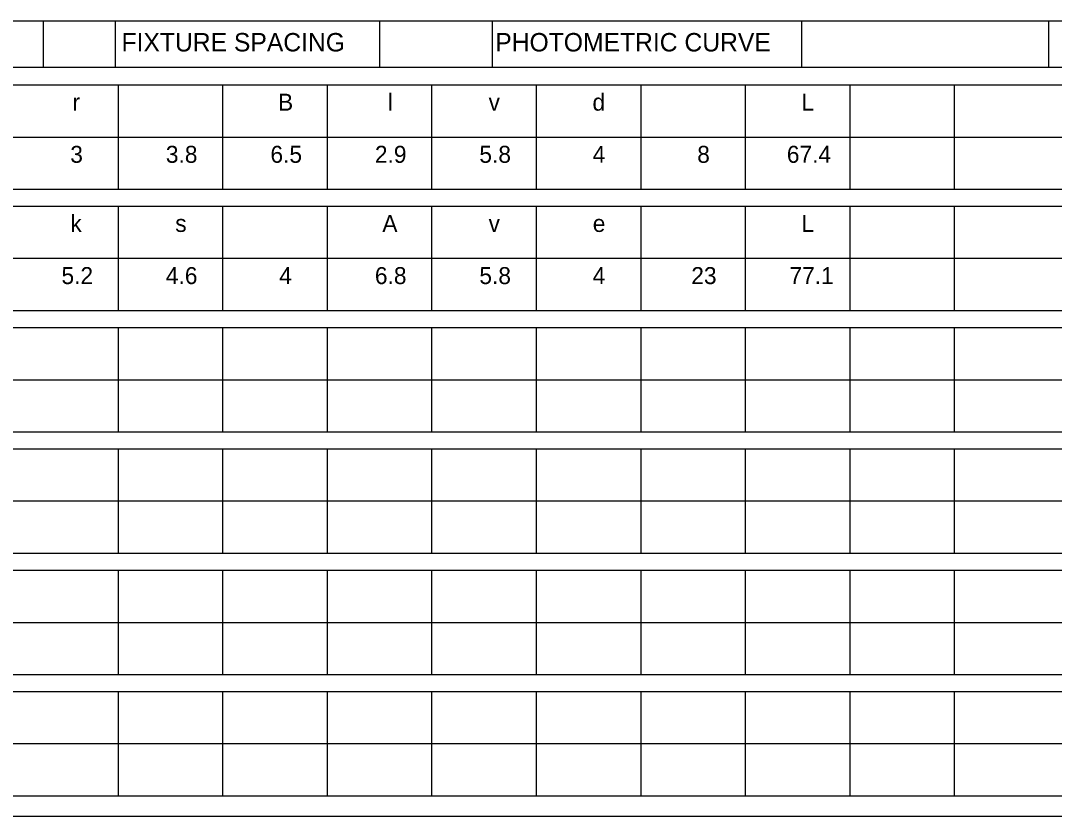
# Model space of a CAD drawing. Extents: x 1374 to 1480, y 568 to 638.
# Drawn here: x 1439.74 to 1450.16, y 587.83 to 595.86 of the extents above; entities that cross this region are included whole.
import ezdxf

# ---------------------------------------------------------------- set-up
doc = ezdxf.new("R2010")
doc.units = 0
for name, color, linetype in [('GSSign', 7, 'Continuous'), ('SheetLinesMisc2_dp', 7, 'Continuous'), ('TextMinor', 7, 'Continuous')]:
    doc.layers.add(name, color=color, linetype=linetype)

msp = doc.modelspace()

# ---------------------------------------------------------------- linework, layer by layer
at = {"layer": 'SheetLinesMisc2_dp'}
for p, q in [((1436.509, 595.855), (1454.417, 595.855)), ((1439.968, 595.855), (1439.968, 595.388)), ((1440.693, 595.855), (1440.693, 595.388)), ((1443.359, 595.855), (1443.359, 595.388)), ((1444.494, 595.855), (1444.494, 595.388)), ((1447.612, 595.855), (1447.612, 595.388)), ((1450.101, 595.855), (1450.101, 595.388)), ((1436.509, 595.388), (1454.417, 595.388)), ((1428.522, 595.208), (1454.417, 595.208)), ((1440.723, 595.208), (1440.723, 594.156)), ((1441.776, 595.208), (1441.776, 594.156)), ((1442.83, 595.208), (1442.83, 594.156)), ((1443.883, 595.208), (1443.883, 594.156)), ((1444.937, 595.208), (1444.937, 594.156)), ((1445.99, 595.208), (1445.99, 594.156)), ((1447.043, 595.208), (1447.043, 594.156)), ((1448.097, 595.208), (1448.097, 594.156)), ((1449.15, 595.208), (1449.15, 594.156)), ((1428.522, 594.682), (1454.417, 594.682)), ((1428.522, 594.156), (1454.417, 594.156)), ((1428.522, 593.985), (1454.417, 593.985)), ((1440.723, 593.985), (1440.723, 592.933)), ((1441.776, 593.985), (1441.776, 592.933)), ((1442.83, 593.985), (1442.83, 592.933)), ((1443.883, 593.985), (1443.883, 592.933)), ((1444.937, 593.985), (1444.937, 592.933)), ((1445.99, 593.985), (1445.99, 592.933)), ((1447.043, 593.985), (1447.043, 592.933)), ((1448.097, 593.985), (1448.097, 592.933)), ((1449.15, 593.985), (1449.15, 592.933)), ((1428.522, 593.459), (1454.417, 593.459)), ((1428.522, 592.933), (1454.417, 592.933)), ((1428.522, 592.761), (1454.417, 592.761)), ((1440.723, 592.761), (1440.723, 591.709)), ((1441.776, 592.761), (1441.776, 591.709)), ((1442.83, 592.761), (1442.83, 591.709)), ((1443.883, 592.761), (1443.883, 591.709)), ((1444.937, 592.761), (1444.937, 591.709)), ((1445.99, 592.761), (1445.99, 591.709)), ((1447.043, 592.761), (1447.043, 591.709)), ((1448.097, 592.761), (1448.097, 591.709)), ((1449.15, 592.761), (1449.15, 591.709)), ((1428.522, 592.235), (1454.417, 592.235)), ((1428.522, 591.709), (1454.417, 591.709)), ((1428.522, 591.538), (1454.417, 591.538)), ((1440.723, 591.538), (1440.723, 590.486)), ((1441.776, 591.538), (1441.776, 590.486)), ((1442.83, 591.538), (1442.83, 590.486)), ((1443.883, 591.538), (1443.883, 590.486)), ((1444.937, 591.538), (1444.937, 590.486)), ((1445.99, 591.538), (1445.99, 590.486)), ((1447.043, 591.538), (1447.043, 590.486)), ((1448.097, 591.538), (1448.097, 590.486)), ((1449.15, 591.538), (1449.15, 590.486)), ((1428.522, 591.012), (1454.417, 591.012)), ((1428.522, 590.486), (1454.417, 590.486)), ((1428.522, 590.314), (1454.417, 590.314)), ((1440.723, 590.314), (1440.723, 589.262)), ((1441.776, 590.314), (1441.776, 589.262)), ((1442.83, 590.314), (1442.83, 589.262)), ((1443.883, 590.314), (1443.883, 589.262)), ((1444.937, 590.314), (1444.937, 589.262)), ((1445.99, 590.314), (1445.99, 589.262)), ((1447.043, 590.314), (1447.043, 589.262)), ((1448.097, 590.314), (1448.097, 589.262)), ((1449.15, 590.314), (1449.15, 589.262)), ((1428.522, 589.788), (1454.417, 589.788)), ((1428.522, 589.262), (1454.417, 589.262)), ((1428.522, 589.09), (1454.417, 589.09)), ((1440.723, 589.09), (1440.723, 588.039)), ((1441.776, 589.09), (1441.776, 588.039)), ((1442.83, 589.09), (1442.83, 588.039)), ((1443.883, 589.09), (1443.883, 588.039)), ((1444.937, 589.09), (1444.937, 588.039)), ((1445.99, 589.09), (1445.99, 588.039)), ((1447.043, 589.09), (1447.043, 588.039)), ((1448.097, 589.09), (1448.097, 588.039)), ((1449.15, 589.09), (1449.15, 588.039)), ((1428.522, 588.565), (1454.417, 588.565)), ((1428.522, 588.039), (1454.417, 588.039)), ((1402.016, 587.832), (1454.669, 587.832))]:
    msp.add_line(p, q, dxfattribs=at)

# ---------------------------------------------------------------- texts
at = {"layer": 'GSSign'}
for s, height, p in [('B', 0.171, (1442.335, 594.948)), ('l', 0.171, (1443.441, 594.948)), ('d', 0.171, (1445.504, 594.948)), ('L', 0.171, (1447.61, 594.948)), ('r', 0.171, (1440.263, 594.948)), ('v', 0.171, (1444.457, 594.948)), ('3', 0.171, (1440.241, 594.422)), ('3.8', 0.1715, (1441.204, 594.422)), ('6.5', 0.1715, (1442.258, 594.422)), ('2.9', 0.1715, (1443.311, 594.422)), ('5.8', 0.1715, (1444.364, 594.422)), ('4', 0.171, (1445.506, 594.422)), ('8', 0.171, (1446.56, 594.422)), ('67.4', 0.1715, (1447.463, 594.422)), ('k', 0.171, (1440.242, 593.725)), ('s', 0.171, (1441.299, 593.725)), ('A', 0.171, (1443.386, 593.725)), ('v', 0.171, (1444.457, 593.725)), ('e', 0.171, (1445.507, 593.725)), ('L', 0.171, (1447.61, 593.725)), ('5.2', 0.1715, (1440.152, 593.199)), ('4.6', 0.1715, (1441.204, 593.199)), ('4', 0.171, (1442.347, 593.199)), ('6.8', 0.1715, (1443.311, 593.199)), ('5.8', 0.1715, (1444.364, 593.199)), ('4', 0.171, (1445.506, 593.199)), ('23', 0.1715, (1446.5, 593.199)), ('77.1', 0.1715, (1447.489, 593.199))]:
    msp.add_text(s, height=height, dxfattribs=at).set_placement(p)
at = {"layer": 'TextMinor'}
for s, p in [('FIXTURE SPACING', (1440.757, 595.545)), ('PHOTOMETRIC CURVE', (1444.524, 595.545))]:
    msp.add_text(s, height=0.18601, dxfattribs=at).set_placement(p)

doc.saveas('drawing.dxf')
